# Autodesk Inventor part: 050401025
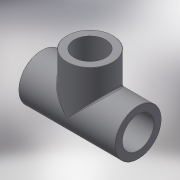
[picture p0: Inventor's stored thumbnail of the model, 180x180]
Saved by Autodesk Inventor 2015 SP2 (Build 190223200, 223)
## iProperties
Created: 2017-10
Part Number: 050401025
Material: Generic
Description: PLASSON THREADED TEE PVC 2.1/2"
Document SubType Name: Modeling
Designer: KIM
Density: 1 g/cm^3
Appearance: Default
Author: KIM
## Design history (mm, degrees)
derived "050401.ipt"
feature "Solid1::050401.ipt"
feature "Solid2::050401.ipt"
tag "TaggingFeature1"
body "Solid1"
other parameters: "d2" = 29, "d4" = 72.226, "d5" = 65.0034, "d7" = 0.72226, "d8" = 29, "d9" = 85, "d15" = 0, "d18" = 72.226, "d24" = 0.72226, "d30" = 72.226, "d31" = 29, "d32" = 0, "d33" = 65.0034, "d35" = 0, "d36" = 3.6113, "G_" = 72.226, "lt_" = 29
